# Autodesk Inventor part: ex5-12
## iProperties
Shininess: 64.0
Length Units: 11272
Angle Units: 11279
Time Units: 11290
Mass Units: 11286
Length Display Precision: 3
Angle Display Precision: 2
Compacted: True
Part Number: ex5-12
Document SubType Name: Modeling
Created: 2002-09
Designer: Elise Moss
Density: 0.0
Volumn: 0.0
Area: 0.0
PropertySet Name: Model Information
Control State: 0
Master: False
Checked Out: False
Author: Elise Moss
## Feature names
1. Extrusion1
2. Hole1
3. TaperEdge1
4. TaperEdge2
